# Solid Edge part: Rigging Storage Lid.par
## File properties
Author: m_hel
Template: Iso Metric Part.par
Last saved by: m_hel
Revision: 15
Application: Solid Edge
Accuracy: 0,990
Username: m_hel
Material: Textured White
Face Style: White painted
Fill Style: ANSI36(Marble)
Virtual Style: ANSI36(Marble)
Grouping: Uncategorized
LibraryName: Custom Materials
Coef. of Thermal Exp: 0.0
Thermal Conductivity: 0.0
Specific Heat: 0.0
Modulus of Elasticity: 0.0
Poisson's Ratio: 0.0
Yield Stress: 0.0
Ultimate Stress: 0.0
Elongation: 0.0
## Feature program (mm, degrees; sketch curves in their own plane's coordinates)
sketch for "unnamed Protrusion 1" plane through (0, 0, 0) normal (0, 0, 1) x-axis (1, 0, 0)
  line (-450, -200) -> (450, -200)
  line (450, -200) -> (450, 200)
  line (450, 200) -> (-450, 200)
  line (-450, 200) -> (-450, -200)
extrude "unnamed Protrusion 1" add finite 50 along -normal
fillet "Round_1" radius 20
fillet "Round_2" radius 20
thinwall "Thinwall_1"  Thickness = 10 mm
sketch for "unnamed Cutout 1" plane through (0, 0, 0) normal (0, 0, 1) x-axis (1, 0, 0)
  circle centre (0, -100) radius 35
extrude "unnamed Cutout 1" cut through along -normal
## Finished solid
Body 1: solid body, 36 faces, 74 edges, 40 vertices.
  Faces by surface: cylinder 17, plane 11, sphere 8
  Edges by curve: line 40, circle 34
Bounding box of the edges (mm; curved faces can reach further): 900.000 x 400.000 x 50.000, from (-450, -200, -50) to (450, 200, 0).
Cylindrical faces by radius (mm): R10 x8, R20 x8, R35 x1
Spherical faces by radius (mm): R10 x4, R20 x4
Planar faces by outward normal: +x 2, +y 2, +z 1, -x 2, -y 2, -z 2
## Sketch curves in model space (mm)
circle centre (0, -100, 0) radius 35
line (450, -200, 0) -> (450, 200, 0)
line (450, 200, 0) -> (-450, 200, 0)
line (-450, 200, 0) -> (-450, -200, 0)
line (-450, -200, 0) -> (450, -200, 0)
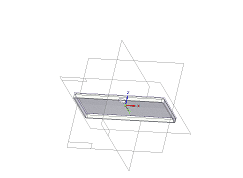
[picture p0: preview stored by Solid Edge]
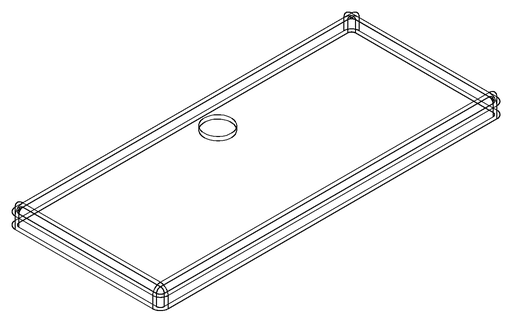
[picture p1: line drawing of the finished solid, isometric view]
